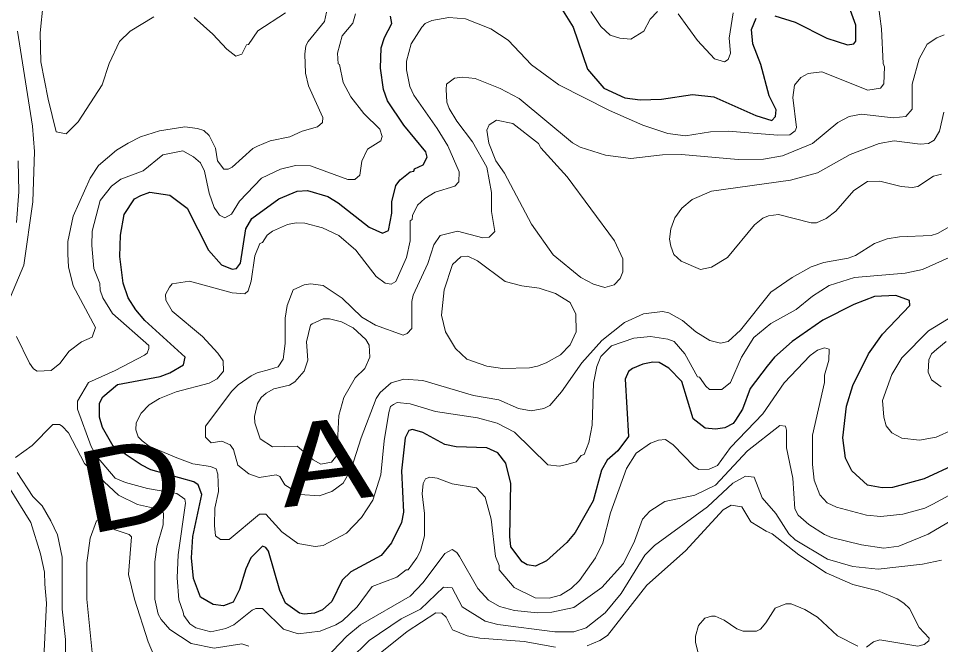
# Model space of a CAD drawing. Extents: x 423 to 448.8, y 7456.3 to 7484.
# Drawn here: x 427.555 to 429.359, y 7468.548 to 7469.772 of the extents above; entities that cross this region are included whole.
import ezdxf
from ezdxf.enums import TextEntityAlignment as Align

# ---------------------------------------------------------------- set-up
doc = ezdxf.new("R2010")
doc.units = 0
doc.header["$LTSCALE"] = 0.032
doc.layers.add('1', color=7, linetype='Continuous', lineweight=25)
doc.layers.add('2', color=7, linetype='Continuous', lineweight=13)
doc.layers.add('61', color=7, linetype='Continuous')

msp = doc.modelspace()

# ---------------------------------------------------------------- linework, layer by layer
at = {"layer": '1'}
for points in [[(429.0346, 7469.7774), (429.0748, 7469.765), (429.1367, 7469.7333), (429.1769, 7469.7202), (429.1893, 7469.7225), (429.1931, 7469.7279), (429.1931, 7469.7588), (429.1529, 7469.871)], [(428.5945, 7469.8285), (428.6401, 7469.755), (428.6687, 7469.673), (428.7004, 7469.6358), (428.7414, 7469.6165), (428.7716, 7469.6126), (428.8134, 7469.6142), (428.8737, 7469.6235), (428.9155, 7469.6188), (428.9975, 7469.5825), (429.0292, 7469.5724), (429.0361, 7469.5802), (429.0377, 7469.5933), (429.0237, 7469.6204), (429.0075, 7469.6823), (428.992, 7469.7225), (428.9889, 7469.7503), (428.9982, 7469.7728)], [(427.9138, 7468.8408), (427.9069, 7468.8601), (427.8983, 7468.8655), (427.8141, 7468.8895), (427.7955, 7468.8988), (427.7406, 7468.9359), (427.7197, 7468.9723), (427.7135, 7468.9924), (427.7135, 7469.0194), (427.7205, 7469.0318), (427.749, 7469.0565), (427.8326, 7469.072), (427.8511, 7469.079), (427.8783, 7469.0945), (427.8813, 7469.1099), (427.8025, 7469.1811), (427.7846, 7469.2019), (427.7699, 7469.2259), (427.7599, 7469.2545), (427.7537, 7469.3064), (427.7545, 7469.3482), (427.7622, 7469.3884), (427.7823, 7469.4193), (427.7947, 7469.4255), (427.8125, 7469.4324), (427.8511, 7469.4263), (427.8852, 7469.4007), (427.927, 7469.3188), (427.9525, 7469.2901), (427.9734, 7469.2816), (427.9819, 7469.2831), (427.9896, 7469.2932), (427.9997, 7469.3605), (428.012, 7469.3806), (428.0646, 7469.4193), (428.1002, 7469.434), (428.1204, 7469.4355), (428.1606, 7469.4239), (428.1807, 7469.4116), (428.241, 7469.3636), (428.2673, 7469.352), (428.2789, 7469.3574), (428.2858, 7469.3915), (428.2858, 7469.4131), (428.2936, 7469.4456), (428.3021, 7469.4564), (428.3214, 7469.4719), (428.3284, 7469.4734), (428.3299, 7469.4781), (428.347, 7469.4858), (428.3547, 7469.5005), (428.3524, 7469.5113), (428.3091, 7469.5631), (428.2773, 7469.6111), (428.2696, 7469.6328), (428.2634, 7469.6746), (428.265, 7469.7148), (428.2712, 7469.7349), (428.2858, 7469.7619), (428.2828, 7469.7767)], [(429.3888, 7468.9003), (429.327, 7468.8717), (429.2651, 7468.8547), (429.245, 7468.8539), (429.2163, 7468.8593), (429.1854, 7468.8872), (429.173, 7468.9119), (429.1676, 7468.9521), (429.1753, 7469.014), (429.1877, 7469.0542), (429.2179, 7469.1161), (429.2457, 7469.1547), (429.2991, 7469.2105), (429.2983, 7469.2205), (429.2713, 7469.2305), (429.2295, 7469.2283), (429.1893, 7469.2128), (429.1289, 7469.1818), (429.0686, 7469.1401), (429.0345, 7469.1099), (429.0199, 7469.0921), (428.9866, 7469.0481), (428.9719, 7469.0078), (428.958, 7468.9862), (428.9533, 7468.98), (428.9371, 7468.9715), (428.9186, 7468.9691), (428.8985, 7468.9707), (428.8752, 7468.9893), (428.8528, 7469.0619), (428.8273, 7469.0883), (428.8087, 7469.0991), (428.7964, 7469.0998), (428.7763, 7469.096), (428.7561, 7469.0875), (428.7484, 7469.0813), (428.7422, 7469.0666), (428.7484, 7468.9544), (428.7275, 7468.9266), (428.7066, 7468.908), (428.6958, 7468.8887), (428.6796, 7468.8284), (428.644, 7468.7665), (428.6277, 7468.7472), (428.5883, 7468.7116), (428.5666, 7468.7007), (428.5504, 7468.7038), (428.5403, 7468.7092), (428.5187, 7468.7387), (428.5163, 7468.7588), (428.5187, 7468.8624), (428.5086, 7468.9026), (428.4931, 7468.9228), (428.4715, 7468.932), (428.4112, 7468.9343), (428.3895, 7468.939), (428.3462, 7468.9622), (428.3261, 7468.9683), (428.3191, 7468.966), (428.3114, 7468.9521), (428.3044, 7468.8872), (428.3083, 7468.8067), (428.3044, 7468.7866), (428.2851, 7468.7464), (428.265, 7468.7216), (428.2054, 7468.6899), (428.1884, 7468.6737), (428.1683, 7468.6319), (428.1497, 7468.6157), (428.1343, 7468.6087), (428.1142, 7468.6072), (428.1049, 7468.6087), (428.0778, 7468.6288), (428.0662, 7468.6536), (428.0445, 7468.7301), (428.0394, 7468.7377), (428.0327, 7468.7403), (428.026, 7468.7332), (428.0097, 7468.717), (427.9997, 7468.6954), (427.9873, 7468.6551), (427.9749, 7468.6304), (427.9564, 7468.6234), (427.9363, 7468.6257), (427.9115, 7468.6404), (427.8976, 7468.6768), (427.8937, 7468.717), (427.896, 7468.7588), (427.9138, 7468.8408)]]:
    msp.add_lwpolyline(points, dxfattribs=at)
at = {"layer": '2'}
for points in [[(427.6037, 7469.8014), (427.5975, 7469.7442), (427.599, 7469.6869), (427.613, 7469.6142), (427.6292, 7469.55), (427.6485, 7469.5461), (427.6718, 7469.5701), (427.7189, 7469.6421), (427.7328, 7469.6838), (427.7529, 7469.7272), (427.7738, 7469.7472), (427.8203, 7469.7751)], [(427.8504, 7469.2468), (427.8558, 7469.253), (427.8899, 7469.2584), (427.9734, 7469.2352), (427.9981, 7469.2337), (428.0043, 7469.2391), (428.0105, 7469.2584), (428.0175, 7469.3079), (428.0275, 7469.3319), (428.0329, 7469.3342), (428.0414, 7469.3482), (428.0523, 7469.3558), (428.0817, 7469.369), (428.0987, 7469.3721), (428.1157, 7469.3714), (428.1497, 7469.3628), (428.1822, 7469.3474), (428.2155, 7469.3187), (428.2549, 7469.2677), (428.2727, 7469.2545), (428.2843, 7469.2522), (428.2936, 7469.2576), (428.3145, 7469.3048), (428.3215, 7469.3373), (428.3215, 7469.376), (428.3253, 7469.379), (428.3261, 7469.3868), (428.3361, 7469.4069), (428.35, 7469.4201), (428.3702, 7469.4324), (428.4088, 7469.4441), (428.4166, 7469.4526), (428.4174, 7469.4719), (428.3949, 7469.523), (428.374, 7469.557), (428.3284, 7469.622), (428.3207, 7469.639), (428.3145, 7469.6715), (428.3145, 7469.6885), (428.3237, 7469.7225), (428.3446, 7469.755), (428.3508, 7469.7619), (428.364, 7469.7681), (428.3973, 7469.7736), (428.4297, 7469.7712), (428.4792, 7469.7519), (428.5133, 7469.7295), (428.5589, 7469.6815), (428.6123, 7469.642), (428.7113, 7469.5918), (428.7763, 7469.5632), (428.8258, 7469.5469), (428.8598, 7469.5423), (428.9093, 7469.55), (428.9433, 7469.5516), (429.0408, 7469.5438), (429.0639, 7469.5446), (429.0748, 7469.5523), (429.0771, 7469.5585), (429.0702, 7469.6173), (429.0732, 7469.6413), (429.0856, 7469.6567), (429.1003, 7469.6645), (429.1266, 7469.6676), (429.2171, 7469.632), (429.2418, 7469.6359), (429.2481, 7469.6444), (429.2496, 7469.6776), (429.2465, 7469.6838), (429.2434, 7469.7519), (429.2372, 7469.8014)], [(427.5511, 7469.1501), (427.5766, 7469.0976), (427.5843, 7469.0867), (427.5921, 7469.0821), (427.6191, 7469.0836), (427.6361, 7469.0975), (427.6547, 7469.1215), (427.6787, 7469.1393), (427.6996, 7469.1486), (427.7058, 7469.1679), (427.6625, 7469.2492), (427.6532, 7469.2863), (427.6516, 7469.311), (427.6516, 7469.3358), (427.6625, 7469.3853), (427.6957, 7469.4595), (427.7119, 7469.4843), (427.7467, 7469.5144), (427.77, 7469.5283), (427.794, 7469.5407), (427.8311, 7469.5523), (427.8806, 7469.56), (427.9053, 7469.557), (427.9177, 7469.5531), (427.9285, 7469.543), (427.9409, 7469.5183), (427.9447, 7469.4936), (427.9571, 7469.4773), (427.9656, 7469.4773), (427.9734, 7469.4812), (428.0136, 7469.5175), (428.0229, 7469.5222), (428.0477, 7469.533), (428.0863, 7469.5407), (428.1103, 7469.5515), (428.1404, 7469.56), (428.1497, 7469.5686), (428.1505, 7469.5786), (428.1226, 7469.6405), (428.1165, 7469.6653), (428.1157, 7469.7024), (428.1172, 7469.7186), (428.1219, 7469.7272), (428.1536, 7469.7658), (428.1575, 7469.7844)], [(428.0198, 7468.618), (428.0121, 7468.6149), (427.9765, 7468.5863), (427.961, 7468.5793), (427.9316, 7468.5723), (427.9022, 7468.5801), (427.8906, 7468.5878), (427.879, 7468.6041), (427.8775, 7468.611), (427.869, 7468.635), (427.8659, 7468.6783), (427.8674, 7468.7232), (427.8821, 7468.8238), (427.8805, 7468.8322), (427.8651, 7468.8431), (427.8079, 7468.8531), (427.7646, 7468.8647), (427.7444, 7468.8732), (427.7081, 7468.9158), (427.6972, 7468.9351), (427.6709, 7469.0078), (427.6709, 7469.0233), (427.6919, 7469.0604), (427.7445, 7469.0836), (427.8016, 7469.1138), (427.8071, 7469.1176), (427.8102, 7469.1269), (427.8102, 7469.1323), (427.739, 7469.195), (427.7204, 7469.2259), (427.7151, 7469.2406), (427.7143, 7469.2538), (427.7027, 7469.2832), (427.6988, 7469.328), (427.6996, 7469.3559), (427.7151, 7469.4162), (427.7375, 7469.444), (427.7553, 7469.4579), (427.7993, 7469.4742), (427.8373, 7469.5051), (427.8767, 7469.5129), (427.8976, 7469.5013), (427.9115, 7469.4897), (427.9193, 7469.4735), (427.9285, 7469.4301), (427.9378, 7469.4023), (427.9486, 7469.3876), (427.9587, 7469.3822), (427.9719, 7469.3891), (427.9873, 7469.4147), (428.0306, 7469.4595), (428.0678, 7469.4773), (428.0972, 7469.4843), (428.1265, 7469.4835), (428.1993, 7469.4572), (428.2132, 7469.4572), (428.2232, 7469.4657), (428.2271, 7469.4928), (428.2379, 7469.5167), (428.2642, 7469.533), (428.2665, 7469.5415), (428.2619, 7469.5554), (428.2309, 7469.5864), (428.2054, 7469.6189), (428.1907, 7469.6467), (428.183, 7469.6822), (428.1807, 7469.683), (428.1791, 7469.7039), (428.1884, 7469.7379), (428.2093, 7469.7627), (428.2147, 7469.7812)], [(427.8991, 7469.7736), (427.9355, 7469.741), (427.9625, 7469.7117), (427.9803, 7469.6985), (427.992, 7469.7024), (428.0012, 7469.7202), (428.0051, 7469.721), (428.0236, 7469.748), (428.0778, 7469.7828)], [(428.6749, 7469.7859), (428.6942, 7469.7565), (428.7128, 7469.7395), (428.7314, 7469.7333), (428.753, 7469.7318), (428.7785, 7469.7473), (428.7909, 7469.7704), (428.8056, 7469.7859)], [(428.8458, 7469.7813), (428.8837, 7469.7287), (428.917, 7469.6931), (428.9363, 7469.6869), (428.9433, 7469.6916), (428.948, 7469.7039), (428.9456, 7469.7333), (428.9534, 7469.7828)], [(427.5534, 7469.7473), (427.5828, 7469.5616), (427.5867, 7469.5121), (427.5836, 7469.4131), (427.5658, 7469.2894), (427.5395, 7469.2275)], [(428.8544, 7469.1811), (428.8273, 7469.1966), (428.8149, 7469.1988), (428.7778, 7469.1942), (428.7407, 7469.1772), (428.6966, 7469.1424), (428.6571, 7469.0983), (428.6177, 7469.0419), (428.5945, 7469.0148), (428.5829, 7469.0094), (428.5581, 7469.0047), (428.5334, 7469.0094), (428.4947, 7469.0264), (428.4452, 7469.0349), (428.3462, 7469.0643), (428.3091, 7469.0666), (428.2843, 7469.0596), (428.2626, 7469.0403), (428.2549, 7469.0287), (428.2255, 7468.9521), (428.2062, 7468.8903), (428.1907, 7468.8632), (428.1683, 7468.8469), (428.1436, 7468.8384), (428.1064, 7468.8408), (428.0762, 7468.8601), (428.0662, 7468.8763), (428.0592, 7468.8794), (428.026, 7468.874), (428.0058, 7468.8817), (427.9842, 7468.8987), (427.9757, 7468.9289), (427.9695, 7468.9382), (427.9533, 7468.9452), (427.9324, 7468.9421), (427.9208, 7468.9529), (427.9208, 7468.9745), (427.9726, 7469.0434), (427.985, 7469.0558), (428.0105, 7469.0728), (428.0221, 7469.079), (428.0461, 7469.0852), (428.0631, 7469.0906), (428.0731, 7469.106), (428.077, 7469.1362), (428.077, 7469.1857), (428.0809, 7469.2105), (428.0925, 7469.2414), (428.1142, 7469.2514), (428.1265, 7469.253), (428.1513, 7469.2499), (428.1884, 7469.2251), (428.2271, 7469.188), (428.2534, 7469.1725), (428.3075, 7469.1524), (428.3153, 7469.1556), (428.3245, 7469.1656), (428.3245, 7469.2182), (428.3276, 7469.2306), (428.3562, 7469.2925), (428.3678, 7469.3296), (428.3802, 7469.3474), (428.4143, 7469.3559), (428.4638, 7469.3427), (428.4761, 7469.3443), (428.487, 7469.3551), (428.4808, 7469.3946), (428.4808, 7469.4317), (428.4715, 7469.4812), (428.4437, 7469.5307), (428.4127, 7469.5709), (428.398, 7469.5957), (428.3934, 7469.608), (428.3918, 7469.6328), (428.3926, 7469.6436), (428.4081, 7469.6552), (428.4236, 7469.6575), (428.4483, 7469.6544), (428.4978, 7469.6351), (428.5349, 7469.6157), (428.6393, 7469.5291), (428.654, 7469.5206), (428.7035, 7469.5044), (428.753, 7469.4982), (428.8149, 7469.5051), (428.8521, 7469.5059), (428.9634, 7469.4959), (429.0129, 7469.4967), (429.0501, 7469.5036), (429.1088, 7469.5276), (429.1583, 7469.5686), (429.18, 7469.5802), (429.2047, 7469.5848), (429.2666, 7469.5778), (429.2914, 7469.5802), (429.3037, 7469.5949), (429.3037, 7469.6436), (429.3169, 7469.6931), (429.3331, 7469.7217), (429.3517, 7469.7341), (429.3664, 7469.7403)], [(429.361, 7469.4672), (429.3455, 7469.4634), (429.3146, 7469.4433), (429.3038, 7469.4417), (429.2821, 7469.4433), (429.2403, 7469.4541), (429.2163, 7469.4533), (429.1892, 7469.4355), (429.1545, 7469.3953), (429.1351, 7469.3806), (429.1166, 7469.3721), (429.1057, 7469.3721), (429.0423, 7469.3884), (429.0222, 7469.386), (429.0114, 7469.3814), (428.9951, 7469.3683), (428.9425, 7469.3048), (428.9108, 7469.2855), (428.8892, 7469.2808), (428.8513, 7469.2971), (428.8373, 7469.3102), (428.8311, 7469.3265), (428.8288, 7469.3404), (428.8311, 7469.3605), (428.8389, 7469.3822), (428.8528, 7469.4007), (428.8729, 7469.4177), (428.9108, 7469.434), (429.0655, 7469.4556), (429.1181, 7469.4704), (429.1823, 7469.5059), (429.2388, 7469.5276), (429.2682, 7469.533), (429.3192, 7469.526), (429.3354, 7469.5276), (429.3463, 7469.5337), (429.3571, 7469.5515), (429.3656, 7469.5887)], [(427.5549, 7469.4936), (427.5557, 7469.4332), (427.5511, 7469.3729)], [(429.4028, 7469.3798), (429.3533, 7469.3512), (429.3409, 7469.3474), (429.279, 7469.3451), (429.2543, 7469.3412), (429.2295, 7469.3319), (429.1924, 7469.3087), (429.1784, 7469.3033), (429.1305, 7469.2948), (429.1057, 7469.2863), (429.0686, 7469.2654), (429.0268, 7469.2368), (428.968, 7469.1625), (428.9433, 7469.1401), (428.9286, 7469.137), (428.9077, 7469.1424), (428.8806, 7469.1594), (428.8544, 7469.1811)], [(429.3888, 7469.3102), (429.3239, 7469.2808), (429.2898, 7469.2739), (429.1908, 7469.2654), (429.1413, 7469.2499), (429.1088, 7469.229), (429.0764, 7469.2027), (429.0269, 7469.1756), (428.9936, 7469.1478), (428.9696, 7469.1099), (428.9479, 7469.0604), (428.9309, 7469.0465), (428.9069, 7469.0465), (428.9, 7469.0527), (428.8876, 7469.0705), (428.8837, 7469.0712), (428.859, 7469.1161), (428.8381, 7469.1401), (428.8258, 7469.1447), (428.7917, 7469.1501), (428.7592, 7469.1471), (428.7151, 7469.1316), (428.6942, 7469.1107), (428.6865, 7469.0914), (428.6803, 7469.0589), (428.6772, 7468.9769), (428.6711, 7468.9429), (428.6618, 7468.9196), (428.6563, 7468.9173), (428.6463, 7468.9049), (428.6308, 7468.9003), (428.6138, 7468.8964), (428.5906, 7468.8988), (428.5256, 7468.9629), (428.4916, 7468.9807), (428.4529, 7468.9908), (428.371, 7469.0032), (428.3215, 7469.0186), (428.2959, 7469.021), (428.289, 7469.0171), (428.2828, 7469.0132), (428.2797, 7469.0016), (428.2704, 7468.946), (428.2642, 7468.8794), (428.2487, 7468.8299), (428.2263, 7468.7959), (428.1969, 7468.7657), (428.1513, 7468.741), (428.1358, 7468.7394), (428.1018, 7468.7449), (428.0701, 7468.768), (428.0391, 7468.8029), (428.0267, 7468.8029), (427.9672, 7468.7533), (427.9502, 7468.7533), (427.9409, 7468.7603), (427.9386, 7468.7804), (427.9394, 7468.8145), (427.9463, 7468.847), (427.9455, 7468.881), (427.9417, 7468.891), (427.9308, 7468.8957), (427.8961, 7468.9011), (427.8651, 7468.9127), (427.811, 7468.9359), (427.797, 7468.9459), (427.7893, 7468.9536), (427.7847, 7468.9676), (427.7854, 7468.9815), (427.7955, 7469.0001), (427.8109, 7469.0163), (427.8311, 7469.0287), (427.8636, 7469.0418), (427.9285, 7469.0588), (427.944, 7469.0674), (427.9564, 7469.0821), (427.9556, 7469.1022), (427.9455, 7469.1177), (427.9154, 7469.1501), (427.8558, 7469.1997), (427.8434, 7469.2213), (427.8427, 7469.2321), (427.8504, 7469.2468)], [(429.2635, 7468.9614), (429.2527, 7468.9753), (429.248, 7468.9924), (429.2457, 7469.0249), (429.2635, 7469.0759), (429.2836, 7469.1084), (429.3354, 7469.161), (429.3942, 7469.1973)], [(429.4306, 7468.8694), (429.344, 7468.8222), (429.3285, 7468.8145), (429.2852, 7468.8028), (429.2419, 7468.7982), (429.214, 7468.8005), (429.1552, 7468.816), (429.1374, 7468.8245), (429.1227, 7468.8407), (429.1119, 7468.8694), (429.1088, 7468.8995), (429.1088, 7468.9568), (429.132, 7469.0604), (429.132, 7469.0744), (429.1405, 7469.1037), (429.1413, 7469.1254), (429.132, 7469.1277), (429.1181, 7469.123), (429.1042, 7469.113), (429.0531, 7469.0596), (429.0114, 7468.9986), (428.948, 7468.9328), (428.9224, 7468.898), (428.9062, 7468.8903), (428.8861, 7468.8902), (428.8768, 7468.8957), (428.8358, 7468.9382), (428.8211, 7468.9483), (428.8072, 7468.9475), (428.7917, 7468.9413), (428.7639, 7468.922), (428.7445, 7468.8918), (428.7136, 7468.8052), (428.6981, 7468.7464), (428.6842, 7468.717), (428.6525, 7468.6729), (428.6362, 7468.6574), (428.6154, 7468.6443), (428.5937, 7468.6381), (428.5659, 7468.6389), (428.5249, 7468.659), (428.4955, 7468.6938), (428.4955, 7468.7023), (428.4885, 7468.7201), (428.48, 7468.7928), (428.4684, 7468.8361), (428.4514, 7468.8539), (428.4034, 7468.8616), (428.3741, 7468.8732), (428.3601, 7468.8748), (428.3516, 7468.8717), (428.347, 7468.8624), (428.3447, 7468.8423), (428.3493, 7468.8036), (428.3493, 7468.7603), (428.3415, 7468.7309), (428.3346, 7468.717), (428.3176, 7468.6938), (428.3137, 7468.6938), (428.2952, 7468.6791), (428.2472, 7468.6613), (428.2178, 7468.6211), (428.1892, 7468.594), (428.176, 7468.5863), (428.1451, 7468.5739), (428.1025, 7468.5685), (428.0739, 7468.5777), (428.0329, 7468.618), (428.0198, 7468.618)], [(429.3602, 7469.0519), (429.3416, 7469.065), (429.3347, 7469.0805), (429.3362, 7469.1045), (429.3416, 7469.1161), (429.3517, 7469.1254), (429.3703, 7469.1401)], [(428.0059, 7468.5445), (427.992, 7468.5491), (427.9378, 7468.5407), (427.893, 7468.5499), (427.8512, 7468.577), (427.8342, 7468.5963), (427.8287, 7468.6072), (427.8218, 7468.6366), (427.8218, 7468.7093), (427.8256, 7468.7387), (427.838, 7468.782), (427.8388, 7468.8051), (427.8172, 7468.8152), (427.7878, 7468.8214), (427.7506, 7468.84), (427.6841, 7468.9018), (427.6531, 7468.9614), (427.6408, 7468.9746), (427.6354, 7468.9777), (427.6222, 7468.9777), (427.582, 7468.9366), (427.5495, 7468.9134)], [(429.3935, 7468.7982), (429.3347, 7468.7634), (429.2775, 7468.7402), (429.2481, 7468.7363), (429.2047, 7468.7425), (429.146, 7468.7572), (429.132, 7468.7626), (429.1011, 7468.7827), (429.0802, 7468.8005), (429.074, 7468.8129), (429.0702, 7468.8733), (429.0578, 7468.932), (429.0578, 7468.9668), (429.0555, 7468.9746), (429.0446, 7468.9761), (428.9812, 7468.9266), (428.9186, 7468.8593), (428.8783, 7468.84), (428.8196, 7468.8276), (428.7902, 7468.8082), (428.7762, 7468.7928), (428.76, 7468.7495), (428.7391, 7468.7062), (428.6966, 7468.659), (428.6417, 7468.6203), (428.5984, 7468.611), (428.5705, 7468.6095), (428.5257, 7468.6141), (428.4963, 7468.6218), (428.4746, 7468.6342), (428.4537, 7468.6574), (428.4181, 7468.7201), (428.4127, 7468.7278), (428.4034, 7468.7332), (428.3895, 7468.7255), (428.3469, 7468.6691), (428.3215, 7468.642), (428.224, 7468.5863), (428.1977, 7468.5638), (428.1002, 7468.4625)], [(429.3826, 7468.9676), (429.3502, 7468.9529), (429.3177, 7468.9475), (429.2836, 7468.9513), (429.2635, 7468.9614)], [(427.5526, 7468.884), (427.5835, 7468.8369), (427.6013, 7468.8191), (427.6183, 7468.7897), (427.6315, 7468.7619), (427.6408, 7468.7186), (427.6408, 7468.6165), (427.647, 7468.5577), (427.647, 7468.5144), (427.6416, 7468.4711), (427.6377, 7468.3396), (427.6307, 7468.3117), (427.6238, 7468.2963)], [(429.361, 7468.7124), (429.3239, 7468.7046), (429.2372, 7468.6953), (429.1877, 7468.7), (429.1382, 7468.7147), (429.0748, 7468.7526), (429.0624, 7468.7642), (429.0369, 7468.8036), (429.0098, 7468.8345), (428.9944, 7468.8748), (428.9774, 7468.8771), (428.9526, 7468.8632), (428.9031, 7468.8168), (428.7994, 7468.741), (428.7808, 7468.7224), (428.7345, 7468.6474), (428.7028, 7468.6095), (428.6656, 7468.5801), (428.6417, 7468.5723), (428.6045, 7468.5723), (428.4932, 7468.5871), (428.4684, 7468.5933), (428.4235, 7468.6211), (428.4034, 7468.6582), (428.3864, 7468.6598), (428.3415, 7468.6165), (428.3036, 7468.5979), (428.241, 7468.5553), (428.2031, 7468.5175)], [(427.5356, 7468.857), (427.5797, 7468.7866), (427.5983, 7468.7247), (427.606, 7468.6892), (427.6067, 7468.666), (427.6099, 7468.6288), (427.6052, 7468.5345), (427.5998, 7468.4989), (427.5929, 7468.4757), (427.5789, 7468.4509), (427.565, 7468.4339), (427.5356, 7468.4223)], [(428.668, 7468.5453), (428.6927, 7468.5553), (428.7074, 7468.5654), (428.7847, 7468.6636), (428.8598, 7468.7309), (428.934, 7468.8113), (428.9495, 7468.8199), (428.9704, 7468.8168), (428.9882, 7468.7874), (429.0176, 7468.7696), (429.0299, 7468.7642), (429.0817, 7468.7232)], [(427.8249, 7468.5159), (427.8086, 7468.553), (427.7823, 7468.6366), (427.7707, 7468.6845), (427.7762, 7468.758), (427.7715, 7468.7626), (427.7444, 7468.7719), (427.7282, 7468.7928), (427.7081, 7468.7897), (427.6957, 7468.7557), (427.6888, 7468.7077), (427.6888, 7468.6366), (427.7065, 7468.4602)], [(429.0817, 7468.7232), (429.1351, 7468.6876), (429.1877, 7468.6652), (429.2372, 7468.6528), (429.2744, 7468.6373), (429.2875, 7468.6288), (429.2983, 7468.618), (429.3169, 7468.5809), (429.337, 7468.56), (429.3362, 7468.5546), (429.327, 7468.5476), (429.3146, 7468.5445), (429.2403, 7468.5569), (429.228, 7468.553), (429.214, 7468.5422)], [(429.197, 7468.5445), (429.1575, 7468.5646), (429.1181, 7468.601), (429.0934, 7468.6164), (429.067, 7468.6273), (429.0562, 7468.6273), (429.0353, 7468.6188), (429.0175, 7468.5902), (429.0067, 7468.5778), (428.999, 7468.5739), (428.9727, 7468.5739), (428.9603, 7468.5785), (428.9356, 7468.5955), (428.9178, 7468.6033), (428.9108, 7468.6033), (428.8977, 7468.5994), (428.8853, 7468.5847), (428.8799, 7468.5639), (428.8799, 7468.5515), (428.8954, 7468.4896)], [(428.2627, 7468.5306), (428.3153, 7468.5731), (428.3717, 7468.6095), (428.3833, 7468.6087), (428.3918, 7468.601), (428.4042, 7468.5762), (428.4328, 7468.5646), (428.4576, 7468.56), (428.5442, 7468.5538), (428.6061, 7468.5422)]]:
    msp.add_lwpolyline(points, dxfattribs=at)
for points in [[(428.5774, 7469.5191), (428.5728, 7469.5276), (428.5225, 7469.5663), (428.4901, 7469.5732), (428.4761, 7469.5639), (428.4715, 7469.5538), (428.4753, 7469.5283), (428.4893, 7469.4936), (428.5063, 7469.4696), (428.5589, 7469.3698), (428.6014, 7469.3095), (428.6556, 7469.2654), (428.6803, 7469.2522), (428.702, 7469.2461), (428.7205, 7469.2514), (428.7321, 7469.2638), (428.7376, 7469.2762), (428.7376, 7469.3017), (428.7213, 7469.3373), (428.6285, 7469.4626)], [(428.5024, 7469.0875), (428.555, 7469.089), (428.5705, 7469.0921), (428.5875, 7469.0983), (428.6154, 7469.1145), (428.6347, 7469.1339), (428.6463, 7469.1594), (428.6455, 7469.1935), (428.6347, 7469.2167), (428.6061, 7469.2344), (428.5736, 7469.2445), (428.5396, 7469.2491), (428.5071, 7469.2576), (428.4529, 7469.2978), (428.4343, 7469.3071), (428.4205, 7469.3056), (428.4042, 7469.2909), (428.388, 7469.2414), (428.3825, 7469.1919), (428.3903, 7469.1594), (428.4104, 7469.1269), (428.432, 7469.106), (428.4715, 7469.0921)], [(428.2139, 7469.0689), (428.2325, 7469.0875), (428.2426, 7469.1099), (428.241, 7469.1331), (428.2348, 7469.144), (428.2101, 7469.1671), (428.1869, 7469.1787), (428.1637, 7469.1849), (428.1513, 7469.1849), (428.1296, 7469.1749), (428.1265, 7469.1725), (428.1188, 7469.1393), (428.1211, 7469.1037), (428.1142, 7469.0821), (428.0956, 7469.0612), (428.0855, 7469.055), (428.0546, 7469.048), (428.0399, 7469.0395), (428.0298, 7469.031), (428.0229, 7469.0187), (428.0167, 7468.9939), (428.0175, 7468.9815), (428.0283, 7468.9498), (428.0523, 7468.9343), (428.1002, 7468.9359), (428.1319, 7468.9088), (428.1466, 7468.9003), (428.1675, 7468.9041), (428.1783, 7468.9173), (428.1822, 7468.9955), (428.1915, 7469.031)]]:
    msp.add_lwpolyline(points, close=True, dxfattribs=at)

# ---------------------------------------------------------------- texts
at = {"layer": '61'}
for s, rotation, width, p in [('A', 6.98, 1.25, (428.1632, 7468.8265)), ('D', 11.31, 1.3, (427.7907, 7468.7825))]:
    msp.add_text(s, height=0.16, rotation=rotation, dxfattribs=dict(at, width=width)).set_placement(p, align=Align.CENTER)

doc.saveas('drawing.dxf')
